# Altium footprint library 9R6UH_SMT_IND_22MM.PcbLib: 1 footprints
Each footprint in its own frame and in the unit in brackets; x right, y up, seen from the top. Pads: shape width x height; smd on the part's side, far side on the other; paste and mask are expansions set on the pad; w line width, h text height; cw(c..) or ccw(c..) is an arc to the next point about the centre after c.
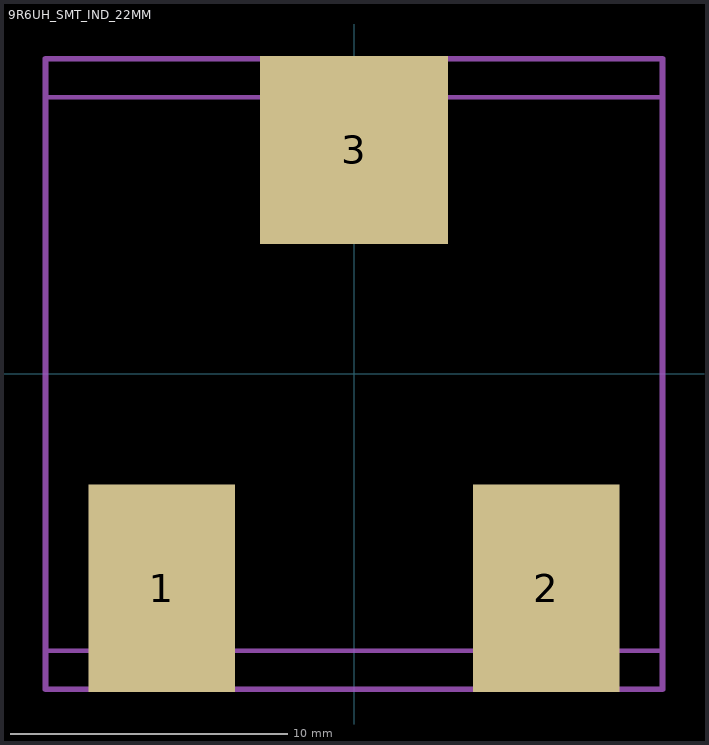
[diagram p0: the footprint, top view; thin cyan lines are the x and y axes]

## 9R6UH_SMT_IND_22MM [mm]
height 14.1
pads (3):
  rect 5.3x7.5 smd paste+0 mask+0: 1(-6.95,-7.75) 2(6.95,-7.75)
  rect 6.8x6.8 smd paste+0 mask+0: 3(0,8.1)
M5 Assembly Top:
  lines w0.15: -11.15,-10 -11.15,10 11.15,10 11.15,-10 -11.15,-10
  lines w0.2: -11.15,-11.4 -11.15,11.4 11.15,11.4 11.15,-11.4 -11.15,-11.4
  text ".Designator" at -3,-0.5 h1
